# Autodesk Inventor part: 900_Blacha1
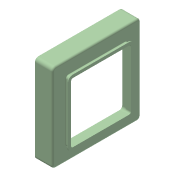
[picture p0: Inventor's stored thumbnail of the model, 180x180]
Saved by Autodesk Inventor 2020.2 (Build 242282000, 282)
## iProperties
Created: 2006-01
Part Number: 900_Blacha1
Document SubType Name: Modeling
Designer: F.Stasiak
Stock Number: Blacha1
Density: 1 g/cm^3
Material: Ogólny
Appearance: Zielony pastelowy
Manager: www.cadconsulting.pl
Company: Fabian Stasiak CAD Consulting
Author: F.Stasiak
Subject: Zbiór ćwiczeń. Autodesk Inventor 2020. Kurs podstawowy
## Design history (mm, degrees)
sketch "Szkic1"
  geometry: L1 (-50, 250)-(50, 250); L2 (50, 250)-(50, -250); L3 (50, -250)-(-50, -250); L4 (-50, -250)-(-50, 250); L5 (0, 250)-(0, -250); 2 further points
  constraints: 10 end point, 3 midpoint, 2 parallel, 1 coincident, 1 horizontal, 1 perpendicular
  dimensions: "d0" = 100 distance of L2.end L3.end; "d1" = 500 distance of L1.end L2.end
extrude "Wyciągnięcie proste1" new body sketch "Szkic1" distance "d2" = 500; taper "d3" = 0 deg
fillet "Zaokrąglenie2" dims "d12" = 20
feature "Skorupa1" dims "d4" = 5
sketch "Szkic2"
  geometry: L1 (-500, 500)-(-500, 0) reference; L2 (0, 500)-(-500, 500) reference; L3 (-420, 80)-(-80, 80); L4 (-80, 80)-(-80, 420); L5 (-80, 420)-(-420, 420); L6 (-420, 420)-(-420, 80)
  constraints: 8 end point, 2 parallel, 1 horizontal, 1 perpendicular
  dimensions: "d5" = 80 distance between parallel lines of L2 L5; "d6" = 80 distance between parallel lines of L1 L6; "d7" = 340 distance of L5.end L3.start; "d8" = 340 distance of L3.start L3.end
extrude "Wyciągnięcie proste2" cut sketch "Szkic2" extent not by distance; stored distance "d9" = 500; taper "d10" = 0 deg
fillet "Zaokrąglenie1" dims "d11" = 10
sketch "Szkic3"
  geometry: L1 (-420, 70)-(-420, 390) reference; L2 (-90, 60)-(-410, 60) reference; L3 (-80, 390)-(-80, 70) reference; L4 (-410, 400)-(-90, 400) reference; L5 (-425, 405)-(-75, 405); L6 (-75, 405)-(-75, 55); L7 (-75, 55)-(-425, 55); L8 (-425, 55)-(-425, 405); A1 r 10 centre (-410, 390) between (-410, 400) and (-420, 390) reference; A2 r 10 centre (-90, 390) between (-80, 390) and (-90, 400) reference; A3 r 10 centre (-90, 70) between (-90, 60) and (-80, 70) reference; A4 r 10 centre (-410, 70) between (-420, 70) and (-410, 60) reference
  constraints: 8 end point, 2 parallel, 1 horizontal, 1 perpendicular
  dimensions: "d13" = 5 distance between parallel lines of L1 L8; "d14" = 5 distance between parallel lines of L5 L4 (= d13); "d15" = 5 distance between parallel lines of L6 L3 (= d13); "d16" = 5 distance between parallel lines of L2 L7 (= d13)
extrude "Wyciągnięcie proste3" join sketch "Szkic3" distance "d17" = 25; taper "d18" = 0 deg
fillet "Zaokrąglenie3" dims "d19" = 15
sketch "Szkic4"
  geometry: L1 (-410, 400)-(-90, 400) reference; L2 (-80, 390)-(-80, 70) reference; L3 (-90, 60)-(-410, 60) reference; L4 (-420, 70)-(-420, 390) reference; L5 (-425, 70)-(-425, 390) reference; L6 (-90, 55)-(-410, 55) reference; L7 (-75, 390)-(-75, 70) reference; L8 (-410, 405)-(-90, 405) reference; L9 (-410, 417)-(-90, 417); L10 (-63, 390)-(-63, 70); L11 (-90, 43)-(-410, 43); L12 (-437, 70)-(-437, 390); A1 r 10 centre (-410, 390) between (-410, 400) and (-420, 390) reference; A2 r 10 centre (-90, 390) between (-80, 390) and (-90, 400) reference; A3 r 10 centre (-90, 70) between (-90, 60) and (-80, 70) reference; A4 r 10 centre (-410, 70) between (-420, 70) and (-410, 60) reference; A5 r 15 centre (-410, 390) between (-410, 405) and (-425, 390) reference; A6 r 15 centre (-410, 70) between (-425, 70) and (-410, 55) reference; A7 r 15 centre (-90, 70) between (-90, 55) and (-75, 70) reference; A8 r 15 centre (-90, 390) between (-75, 390) and (-90, 405) reference; A9 r 27 centre (-410, 390) between (-410, 417) and (-437, 390); A10 r 27 centre (-90, 390) between (-63, 390) and (-90, 417); A11 r 27 centre (-90, 70) between (-90, 43) and (-63, 70); A12 r 27 centre (-410, 70) between (-437, 70) and (-410, 43)
  constraints: 8 end point, 8 point on circle, 4 centre point, 7 other
  dimensions: "d20" = 12 distance between parallel lines of L12 L5
extrude "Wyciągnięcie proste4" join sketch "Szkic4" distance "d21" = 5; taper "d22" = 0 deg
fillet "Zaokrąglenie4" dims "d23" = 10
fillet "Zaokrąglenie5" dims "d24" = 3
node "Bryła1"
node "Korpusy bryłowe"
node "Korpusy powierzchniowe"
